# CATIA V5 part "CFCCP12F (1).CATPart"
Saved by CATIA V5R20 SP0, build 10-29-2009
Part number: CFCCP12F (1)
Revision: TUTTO
Definition: NON CONOSCIUTO
Nomenclature: CFCCP12F (1)
Source: Unknown
Bounding box of the stored display mesh (mm): x -60 to 60, y -39 to 39, z -50 to 0
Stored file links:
  C:\Users\Utente\Desktop\IO LAVORO\3D X SITO CF\X 3D SITO CF 27-09-2020\CFCCP\CFCCP12F\CFCCP12F (1).CATPart
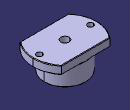
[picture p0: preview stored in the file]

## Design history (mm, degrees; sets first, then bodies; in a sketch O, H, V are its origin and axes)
Body1 "Foro Ø11.0 (11)-1" (main body)
  Solid1: solid without history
